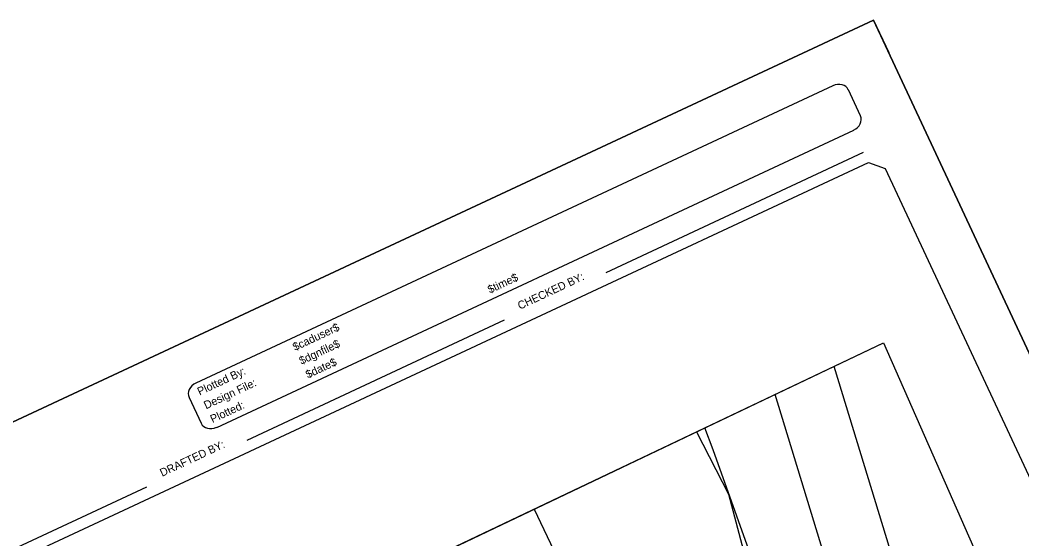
# Model space of a CAD drawing. Extents: x 1040814 to 1041501, y 1126274 to 1127077.
# Drawn here: x 1041044.8 to 1041242.1, y 1126974.4 to 1127076.7 of the extents above; entities that cross this region are included whole.
import ezdxf

# ---------------------------------------------------------------- set-up
doc = ezdxf.new("R2010")
doc.units = 0
for name, color, linetype in [('clip boundary', 7, 'Continuous'), ('LAM', 7, 'Continuous'), ('LELB', 7, 'Continuous'), ('MHB', 7, 'Continuous'), ('NBS_P', 7, 'Continuous'), ('NBS_P_T', 7, 'Continuous'), ('NML_P', 7, 'Continuous'), ('SHEET_BORDER', 7, 'Continuous'), ('SHEET_BORDER_CUT', 7, 'Continuous'), ('SHEET_BORDER_TEXT', 7, 'Continuous')]:
    doc.layers.add(name, color=color, linetype=linetype)

msp = doc.modelspace()

# ---------------------------------------------------------------- linework, layer by layer
at = {"layer": 'clip boundary'}
for points in [[(1041212.91, 1127076.67), (1041500.71, 1126460.57), (1041102.06, 1126274.35), (1040814.26, 1126890.45)], [(1041214.88, 1127013.05), (1041436.47, 1126509.64), (1041196.3, 1126394.87), (1040940.57, 1126882.48)]]:
    msp.add_lwpolyline(points, close=True, dxfattribs=at)
at = {"layer": 'LAM'}
for points in [[(1041254.78, 1126777.09), (1041237.34, 1126848.88), (1041223.61, 1126895.73), (1041224.21, 1126946.09), (1041205.17, 1127008.43)], [(1041178.07, 1126995.53), (1041184.35, 1126983.26), (1041193.48, 1126948.75), (1041202.81, 1126927.03), (1041215.34, 1126892.52), (1041229.72, 1126845.87), (1041245.84, 1126790.43)]]:
    msp.add_lwpolyline(points, dxfattribs=at)
at = {"layer": 'LELB'}
msp.add_lwpolyline([(1041146.07, 1126980.3), (1041167.77, 1126934.56), (1041192.01, 1126888.74), (1041214.15, 1126847.53), (1041233.99, 1126818.61), (1041228.67, 1126851.95), (1041212.83, 1126899.47), (1041200.3, 1126938.77), (1041181.33, 1126991.97), (1041179.68, 1126996.3)], dxfattribs=at)
at = {"layer": 'MHB'}
msp.add_lwpolyline([(1041273.77, 1126564.22), (1041288, 1126693.29), (1041193.5, 1127002.88)], dxfattribs=at)
at = {"layer": 'NBS_P'}
for p, q in [((1041204.9, 1127063.73), (1041079.46, 1127005.13)), ((1041210.34, 1127057.81), (1041207.94, 1127062.94)), ((1041083.55, 1126996.37), (1041208.99, 1127054.97)), ((1041078.1, 1127002.29), (1041080.48, 1126997.2))]:
    msp.add_line(p, q, dxfattribs=at)
for centre, major_axis, start_param, end_param in [((1041205.74, 1127061.92), (2.19, 1.02), 0, 1.570796), ((1041208.14, 1127056.78), (2.19, 1.02), 4.712389, 6.283185), ((1041080.3, 1127003.32), (-2.19, -1.02), 4.712389, 6.283185), ((1041082.68, 1126998.23), (-2.19, -1.02), 0, 1.570796)]:
    msp.add_ellipse(centre, major_axis=major_axis, ratio=0.825959, start_param=start_param, end_param=end_param, dxfattribs=at)
at = {"layer": 'NML_P'}
msp.add_line((1040940.57, 1126882.48), (1041214.88, 1127013.05), dxfattribs=at)
at = {"layer": 'SHEET_BORDER'}
for p, q in [((1041160.27, 1127026.95), (1041210.94, 1127050.62)), ((1041089.55, 1126993.91), (1041140.22, 1127017.58)), ((1041019.1, 1126961), (1041069.77, 1126984.67))]:
    msp.add_line(p, q, dxfattribs=at)
msp.add_lwpolyline([(1041103.08, 1126302.42), (1041099.76, 1126303.63), (1040835.24, 1126869.9), (1040836.45, 1126873.22), (1041211.88, 1127048.6), (1041215.2, 1127047.39), (1041479.72, 1126481.12), (1041478.52, 1126477.8)], close=True, dxfattribs=at)
at = {"layer": 'SHEET_BORDER_CUT'}
msp.add_lwpolyline([(1040814.26, 1126890.45), (1041102.06, 1126274.35), (1041500.71, 1126460.57), (1041212.91, 1127076.67)], close=True, dxfattribs=at)
msp.add_lwpolyline([(1041206.5, 1127073.68), (1041212.91, 1127076.67), (1041215.9, 1127070.26)], dxfattribs=at)

# ---------------------------------------------------------------- texts
at = {"layer": 'NBS_P_T'}
for s, height, p in [('$time$', 1.576, (1041137.36, 1127022.75)), ('$caduser$', 1.576, (1041098.97, 1127011.43)), ('$dgnfile$', 1.576, (1041100.24, 1127008.72)), ('$date$', 1.576, (1041101.51, 1127006.01)), ('Plotted By:', 1.5759, (1041080.19, 1127002.66)), ('Design File:', 1.5759, (1041081.46, 1126999.95)), ('Plotted:', 1.576, (1041082.73, 1126997.23))]:
    msp.add_text(s, height=height, rotation=25.0392, dxfattribs=at).set_placement(p)
at = {"layer": 'SHEET_BORDER_TEXT'}
for s, p in [('CHECKED BY:', (1041143.26, 1127019.57)), ('DRAFTED BY:', (1041072.81, 1126986.66))]:
    msp.add_text(s, height=1.5625, rotation=25.0387, dxfattribs=at).set_placement(p)

doc.saveas('drawing.dxf')
